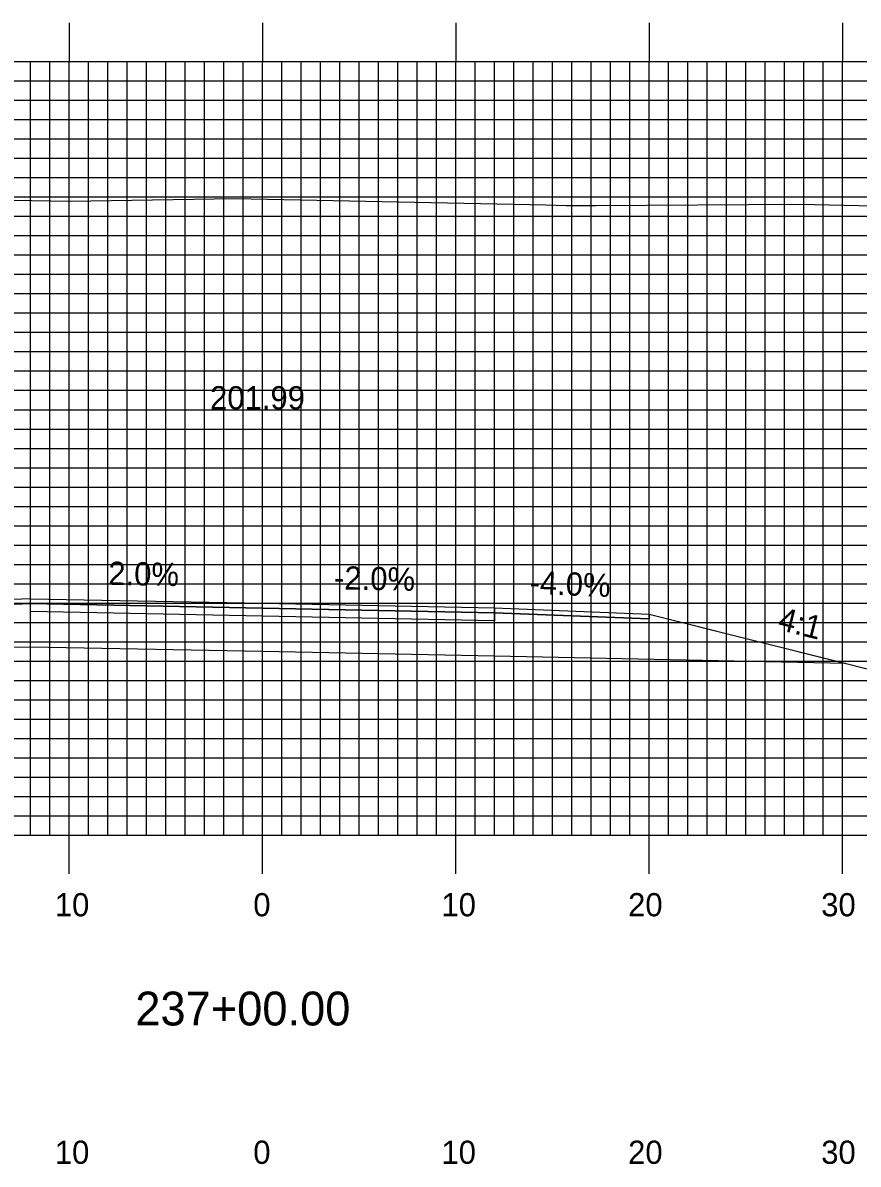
# Model space of a CAD drawing. Extents: x 1800749 to 1801092, y 442591 to 442811.
# Drawn here: x 1800902.1 to 1800945.4, y 442711.6 to 442770.7 of the extents above; entities that cross this region are included whole.
import ezdxf

# ---------------------------------------------------------------- set-up
doc = ezdxf.new("R2010")
doc.units = 0
for name, color, linetype in [('ANNOTATION', 7, 'Continuous'), ('D_Roadway_Centerline', 7, 'Continuous'), ('D_Roadway_Centerline_Text', 7, 'Continuous'), ('D_Roadway_Edge_Shoulder', 7, 'Continuous'), ('D_Roadway_Edge_TW', 7, 'Continuous'), ('D_Roadway_Pavement', 7, 'Continuous'), ('D_Roadway_SlopeLines', 7, 'Continuous'), ('D_Roadway_SubGrade', 7, 'Continuous'), ('H_V ANNOTATION', 7, 'Continuous'), ('MAJOR', 7, 'Continuous'), ('MINOR', 7, 'Continuous'), ('S_Roadway_Centerline', 7, 'Continuous')]:
    doc.layers.add(name, color=color, linetype=linetype)

msp = doc.modelspace()

# ---------------------------------------------------------------- linework, layer by layer
at = {"layer": 'D_Roadway_Edge_Shoulder'}
for points in [[(1800902.549, 442740.891), (1800894.549, 442740.571), (1800894.549, 442740.321), (1800902.549, 442740.641)], [(1800926.549, 442740.411), (1800934.549, 442740.091), (1800934.549, 442739.841), (1800926.549, 442740.161)]]:
    msp.add_lwpolyline(points, close=True, dxfattribs=at)
at = {"layer": 'D_Roadway_Edge_TW'}
msp.add_lwpolyline([(1800902.549, 442740.641), (1800902.549, 442740.891), (1800914.549, 442740.651), (1800926.549, 442740.411), (1800926.549, 442740.161), (1800914.549, 442740.401)], close=True, dxfattribs=at)
at = {"layer": 'D_Roadway_Pavement'}
msp.add_lwpolyline([(1800902.549, 442740.224), (1800902.549, 442740.641), (1800914.549, 442740.401), (1800926.549, 442740.161), (1800926.549, 442739.744), (1800914.549, 442739.984)], close=True, dxfattribs=at)
at = {"layer": 'D_Roadway_SlopeLines'}
msp.add_lwpolyline([(1800934.549, 442740.091), (1800948.723, 442736.547)], dxfattribs=at)
at = {"layer": 'D_Roadway_SubGrade'}
msp.add_lwpolyline([(1800902.549, 442738.391), (1800884.375, 442738.027), (1800894.549, 442740.571), (1800894.549, 442740.321), (1800902.549, 442740.641), (1800914.549, 442740.401), (1800926.549, 442740.161), (1800934.549, 442739.841), (1800934.549, 442740.091), (1800944.723, 442737.547), (1800926.549, 442737.911), (1800914.549, 442738.151)], close=True, dxfattribs=at)
at = {"layer": 'MAJOR'}
for p, q in [((1800904.549, 442770.669), (1800904.549, 442768.665)), ((1800914.549, 442770.669), (1800914.549, 442768.665)), ((1800924.549, 442770.669), (1800924.549, 442768.665)), ((1800934.549, 442770.669), (1800934.549, 442768.665)), ((1800944.549, 442770.669), (1800944.549, 442768.665)), ((1800774.549, 442768.665), (1801054.549, 442768.665)), ((1800774.549, 442768.665), (1801054.549, 442768.665)), ((1800904.549, 442728.665), (1800904.549, 442768.665)), ((1800914.549, 442728.665), (1800914.549, 442768.665)), ((1800924.549, 442728.665), (1800924.549, 442768.665)), ((1800934.549, 442728.665), (1800934.549, 442768.665)), ((1800944.549, 442728.665), (1800944.549, 442768.665)), ((1800774.549, 442763.665), (1801054.549, 442763.665)), ((1800774.549, 442758.665), (1801054.549, 442758.665)), ((1800774.549, 442753.665), (1801054.549, 442753.665)), ((1800774.549, 442748.665), (1801054.549, 442748.665)), ((1800774.549, 442743.665), (1801054.549, 442743.665)), ((1800774.549, 442738.665), (1801054.549, 442738.665)), ((1800774.549, 442733.665), (1801054.549, 442733.665)), ((1800774.549, 442728.665), (1801054.549, 442728.665)), ((1800774.549, 442728.665), (1801054.549, 442728.665)), ((1800904.549, 442726.661), (1800904.549, 442728.665)), ((1800914.549, 442726.661), (1800914.549, 442728.665)), ((1800924.549, 442726.661), (1800924.549, 442728.665)), ((1800934.549, 442726.661), (1800934.549, 442728.665)), ((1800944.549, 442726.661), (1800944.549, 442728.665))]:
    msp.add_line(p, q, dxfattribs=at)
at = {"layer": 'MINOR'}
for p, q in [((1800902.549, 442728.665), (1800902.549, 442768.665)), ((1800903.549, 442728.665), (1800903.549, 442768.665)), ((1800905.549, 442728.665), (1800905.549, 442768.665)), ((1800906.549, 442728.665), (1800906.549, 442768.665)), ((1800907.549, 442728.665), (1800907.549, 442768.665)), ((1800908.549, 442728.665), (1800908.549, 442768.665)), ((1800909.549, 442728.665), (1800909.549, 442768.665)), ((1800910.549, 442728.665), (1800910.549, 442768.665)), ((1800911.549, 442728.665), (1800911.549, 442768.665)), ((1800912.549, 442728.665), (1800912.549, 442768.665)), ((1800913.549, 442728.665), (1800913.549, 442768.665)), ((1800915.549, 442728.665), (1800915.549, 442768.665)), ((1800916.549, 442728.665), (1800916.549, 442768.665)), ((1800917.549, 442728.665), (1800917.549, 442768.665)), ((1800918.549, 442728.665), (1800918.549, 442768.665)), ((1800919.549, 442728.665), (1800919.549, 442768.665)), ((1800920.549, 442728.665), (1800920.549, 442768.665)), ((1800921.549, 442728.665), (1800921.549, 442768.665)), ((1800922.549, 442728.665), (1800922.549, 442768.665)), ((1800923.549, 442728.665), (1800923.549, 442768.665)), ((1800925.549, 442728.665), (1800925.549, 442768.665)), ((1800926.549, 442728.665), (1800926.549, 442768.665)), ((1800927.549, 442728.665), (1800927.549, 442768.665)), ((1800928.549, 442728.665), (1800928.549, 442768.665)), ((1800929.549, 442728.665), (1800929.549, 442768.665)), ((1800930.549, 442728.665), (1800930.549, 442768.665)), ((1800931.549, 442728.665), (1800931.549, 442768.665)), ((1800932.549, 442728.665), (1800932.549, 442768.665)), ((1800933.549, 442728.665), (1800933.549, 442768.665)), ((1800935.549, 442728.665), (1800935.549, 442768.665)), ((1800936.549, 442728.665), (1800936.549, 442768.665)), ((1800937.549, 442728.665), (1800937.549, 442768.665)), ((1800938.549, 442728.665), (1800938.549, 442768.665)), ((1800939.549, 442728.665), (1800939.549, 442768.665)), ((1800940.549, 442728.665), (1800940.549, 442768.665)), ((1800941.549, 442728.665), (1800941.549, 442768.665)), ((1800942.549, 442728.665), (1800942.549, 442768.665)), ((1800943.549, 442728.665), (1800943.549, 442768.665)), ((1800774.549, 442767.665), (1801054.549, 442767.665)), ((1800774.549, 442766.665), (1801054.549, 442766.665)), ((1800774.549, 442765.665), (1801054.549, 442765.665)), ((1800774.549, 442764.665), (1801054.549, 442764.665)), ((1800774.549, 442762.665), (1801054.549, 442762.665)), ((1800774.549, 442761.665), (1801054.549, 442761.665)), ((1800774.549, 442760.665), (1801054.549, 442760.665)), ((1800774.549, 442759.665), (1801054.549, 442759.665)), ((1800774.549, 442757.665), (1801054.549, 442757.665)), ((1800774.549, 442756.665), (1801054.549, 442756.665)), ((1800774.549, 442755.665), (1801054.549, 442755.665)), ((1800774.549, 442754.665), (1801054.549, 442754.665)), ((1800774.549, 442752.665), (1801054.549, 442752.665)), ((1800774.549, 442751.665), (1801054.549, 442751.665)), ((1800774.549, 442750.665), (1801054.549, 442750.665)), ((1800774.549, 442749.665), (1801054.549, 442749.665)), ((1800774.549, 442747.665), (1801054.549, 442747.665)), ((1800774.549, 442746.665), (1801054.549, 442746.665)), ((1800774.549, 442745.665), (1801054.549, 442745.665)), ((1800774.549, 442744.665), (1801054.549, 442744.665)), ((1800774.549, 442742.665), (1801054.549, 442742.665)), ((1800774.549, 442741.665), (1801054.549, 442741.665)), ((1800774.549, 442740.665), (1801054.549, 442740.665)), ((1800774.549, 442739.665), (1801054.549, 442739.665)), ((1800774.549, 442737.665), (1801054.549, 442737.665)), ((1800774.549, 442736.665), (1801054.549, 442736.665)), ((1800774.549, 442735.665), (1801054.549, 442735.665)), ((1800774.549, 442734.665), (1801054.549, 442734.665)), ((1800774.549, 442732.665), (1801054.549, 442732.665)), ((1800774.549, 442731.665), (1801054.549, 442731.665)), ((1800774.549, 442730.665), (1801054.549, 442730.665)), ((1800774.549, 442729.665), (1801054.549, 442729.665))]:
    msp.add_line(p, q, dxfattribs=at)
at = {"layer": 'S_Roadway_Centerline'}
msp.add_lwpolyline([(1800866.1, 442761.904), (1800875.807, 442761.911), (1800883.239, 442761.453), (1800885.214, 442761.45), (1800887.306, 442761.449), (1800894.628, 442761.623), (1800904.587, 442761.45), (1800913.116, 442761.584), (1800929.195, 442761.256), (1800930.25, 442761.216), (1800931.784, 442761.218), (1800942.325, 442761.297), (1800947.724, 442761.167), (1800953.393, 442761.434), (1800961.402, 442761.623), (1800969.813, 442761.349), (1800978.864, 442761.572), (1800980.005, 442761.672), (1800982.683, 442761.738), (1801004.152, 442760.964)], dxfattribs=at)

# ---------------------------------------------------------------- texts
at = {"layer": 'ANNOTATION'}
for s, rotation, p in [('2.0%', 358.85424, (1800906.556, 442741.611)), ('-2.0%', 358.85424, (1800918.235, 442741.377)), ('-4.0%', 357.70939, (1800928.341, 442741.141)), ('4:1', 345.96376, (1800941.142, 442739.304))]:
    msp.add_text(s, height=1.2, rotation=rotation, dxfattribs=at).set_placement(p)
at = {"layer": 'D_Roadway_Centerline'}
for s, p in [('C', (1800914.544, 442740.651)), ('L', (1800914.549, 442740.643))]:
    msp.add_text(s, height=0.0146, dxfattribs=at).set_placement(p)
at = {"layer": 'D_Roadway_Centerline_Text'}
msp.add_text('201.99', height=1.2, dxfattribs=at).set_placement((1800911.831, 442750.681))
at = {"layer": 'H_V ANNOTATION'}
for s, height, p in [('10', 1.2, (1800903.8, 442724.465)), ('0', 1.2, (1800914.067, 442724.465)), ('10', 1.2, (1800923.8, 442724.465)), ('20', 1.2, (1800933.457, 442724.465)), ('30', 1.2, (1800943.447, 442724.465)), ('237+00.00', 1.75, (1800907.963, 442718.821)), ('10', 1.2, (1800903.8, 442711.665)), ('0', 1.2, (1800914.067, 442711.665)), ('10', 1.2, (1800923.8, 442711.665)), ('20', 1.2, (1800933.457, 442711.665)), ('30', 1.2, (1800943.447, 442711.665))]:
    msp.add_text(s, height=height, dxfattribs=at).set_placement(p)

doc.saveas('drawing.dxf')
